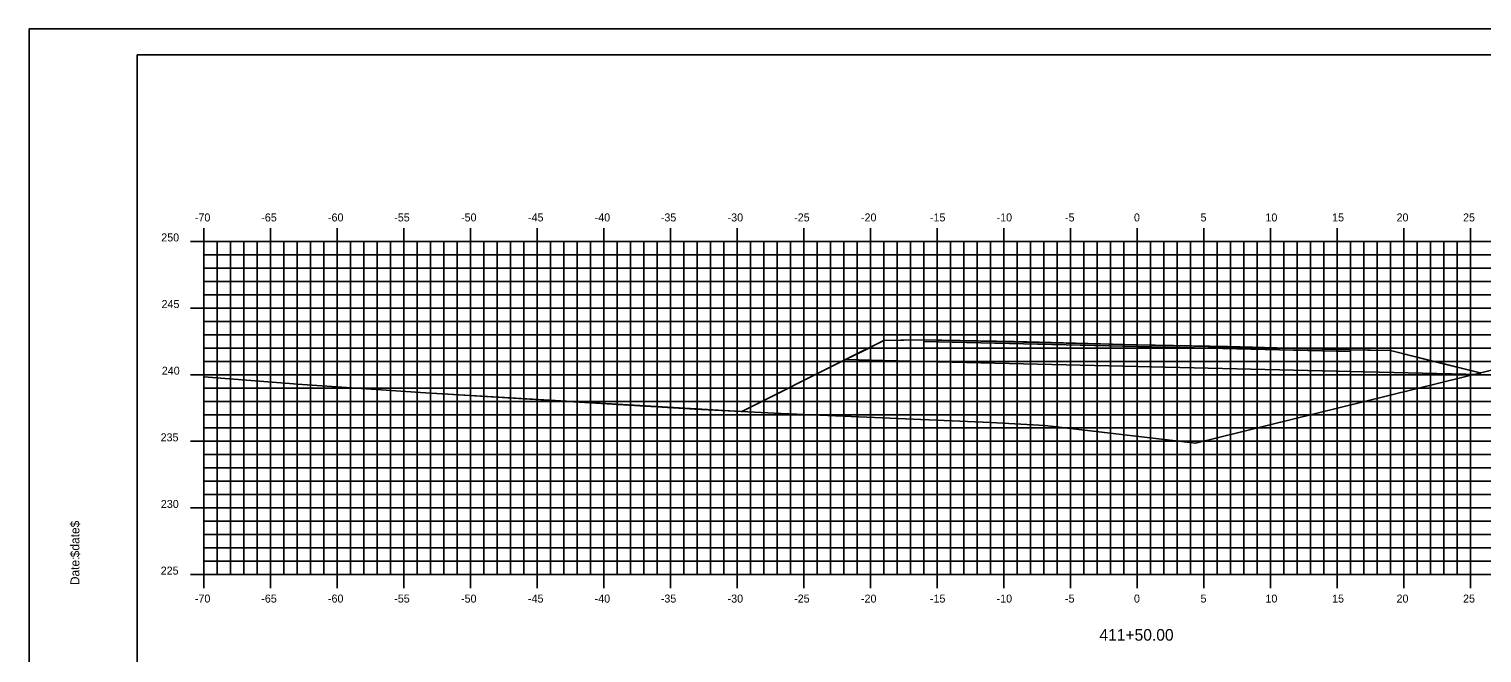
# Model space of a CAD drawing. Extents: x 1168600 to 1177589, y 610178 to 611246.
# Drawn here: x 1172219.5 to 1172328.4, y 610963.7 to 611010.5 of the extents above; entities that cross this region are included whole.
import ezdxf

# ---------------------------------------------------------------- set-up
doc = ezdxf.new("R2010")
doc.units = 0
for name, color, linetype in [('_Construction', 7, 'Continuous'), ('_Station Equation', 7, 'Continuous'), ('D_Roadway_Edge_TW', 7, 'Continuous'), ('D_Roadway_SubGrade', 7, 'Continuous'), ('D_Slope_Direction', 7, 'Continuous'), ('D_Text_Standard', 7, 'Continuous'), ('DIMENSIONS', 7, 'Continuous'), ('H_V ANNOTATION', 7, 'Continuous'), ('MAJOR', 7, 'Continuous'), ('MATCH LINES', 7, 'Continuous'), ('MINOR', 7, 'Continuous')]:
    doc.layers.add(name, color=color, linetype=linetype)

msp = doc.modelspace()

# ---------------------------------------------------------------- linework, layer by layer
at = {"layer": '_Construction'}
for p, q in [((1172387.56, 611008.6), (1172227.56, 611008.6)), ((1172227.56, 611008.6), (1172227.56, 610903.6))]:
    msp.add_line(p, q, dxfattribs=at)
msp.add_lwpolyline([(1172219.47, 610900.54), (1172389.47, 610900.54), (1172389.47, 611010.54), (1172219.47, 611010.54)], close=True, dxfattribs=at)
at = {"layer": '_Station Equation'}
for points in [[(1172232.56, 610984.43), (1172239.95, 610983.87), (1172249.2, 610983.24), (1172272.87, 610981.85), (1172272.87, 610981.85), (1172272.92, 610981.84), (1172280.7, 610985.74), (1172281.93, 610986.35), (1172283.56, 610987.16), (1172284.83, 610987.19), (1172286.56, 610987.22), (1172293.35, 610987.09), (1172302.56, 610986.85), (1172309.35, 610986.71), (1172318.56, 610986.47), (1172319.83, 610986.45), (1172321.56, 610986.41), (1172323.23, 610985.99), (1172324.01, 610985.8), (1172324.91, 610985.57), (1172328.27, 610984.73), (1172328.32, 610984.75), (1172328.33, 610984.75), (1172332.38, 610985.75)], [(1172232.56, 610984.43), (1172239.95, 610983.87), (1172249.2, 610983.24), (1172269.38, 610982.02), (1172275.87, 610981.7), (1172291.59, 610981.02), (1172295.63, 610980.79), (1172305.24, 610979.65), (1172306.94, 610979.46), (1172332.38, 610985.75)]]:
    msp.add_lwpolyline(points, dxfattribs=at)
at = {"layer": 'D_Roadway_Edge_TW'}
msp.add_lwpolyline([(1172318.56, 610986.35), (1172318.56, 610986.47), (1172302.56, 610986.85), (1172286.56, 610987.22), (1172286.56, 610987.1), (1172302.56, 610986.72)], close=True, dxfattribs=at)
at = {"layer": 'D_Roadway_SubGrade'}
for points in [[(1172286.56, 610987.22), (1172283.56, 610987.16), (1172280.7, 610985.74), (1172286.56, 610985.6)], [(1172318.56, 610984.85), (1172318.56, 610986.35), (1172302.56, 610986.72), (1172286.56, 610987.1), (1172286.56, 610985.6), (1172302.56, 610985.22)], [(1172318.56, 610986.47), (1172321.56, 610986.41), (1172328.27, 610984.73), (1172328.27, 610984.62), (1172318.56, 610984.85)]]:
    msp.add_lwpolyline(points, close=True, dxfattribs=at)
at = {"layer": 'D_Slope_Direction'}
msp.add_lwpolyline([(1172321.56, 610986.41), (1172328.27, 610984.73)], dxfattribs=at)
at = {"layer": 'D_Text_Standard'}
msp.add_lwpolyline([(1172272.92, 610981.84), (1172280.7, 610985.74), (1172281.93, 610986.35), (1172283.56, 610987.16), (1172284.83, 610987.19), (1172286.56, 610987.22), (1172293.35, 610987.09), (1172302.56, 610986.85), (1172309.35, 610986.71), (1172318.56, 610986.47), (1172319.83, 610986.45), (1172321.56, 610986.41), (1172323.23, 610985.99), (1172324.01, 610985.8), (1172324.91, 610985.57), (1172328.27, 610984.73)], dxfattribs=at)
at = {"layer": 'DIMENSIONS'}
msp.add_lwpolyline([(1172318.56, 610986.35), (1172318.56, 610986.35), (1172302.56, 610986.72), (1172286.56, 610987.1), (1172286.56, 610987.1), (1172302.56, 610986.72)], close=True, dxfattribs=at)
for points in [[(1172286.56, 610987.1), (1172286.56, 610987.1)], [(1172286.56, 610987.1), (1172286.56, 610987.1)], [(1172318.56, 610986.35), (1172318.56, 610986.35)], [(1172318.56, 610986.35), (1172318.56, 610986.35)]]:
    msp.add_lwpolyline(points, dxfattribs=at)
at = {"layer": 'MAJOR'}
for p, q in [((1172232.56, 610995.6), (1172232.56, 610994.6)), ((1172237.56, 610995.6), (1172237.56, 610994.6)), ((1172242.56, 610995.6), (1172242.56, 610994.6)), ((1172247.56, 610995.6), (1172247.56, 610994.6)), ((1172252.56, 610995.6), (1172252.56, 610994.6)), ((1172257.56, 610995.6), (1172257.56, 610994.6)), ((1172262.56, 610995.6), (1172262.56, 610994.6)), ((1172267.56, 610995.6), (1172267.56, 610994.6)), ((1172272.56, 610995.6), (1172272.56, 610994.6)), ((1172277.56, 610995.6), (1172277.56, 610994.6)), ((1172282.56, 610995.6), (1172282.56, 610994.6)), ((1172287.56, 610995.6), (1172287.56, 610994.6)), ((1172292.56, 610995.6), (1172292.56, 610994.6)), ((1172297.56, 610995.6), (1172297.56, 610994.6)), ((1172302.56, 610995.6), (1172302.56, 610994.6)), ((1172307.56, 610995.6), (1172307.56, 610994.6)), ((1172312.56, 610995.6), (1172312.56, 610994.6)), ((1172317.56, 610995.6), (1172317.56, 610994.6)), ((1172322.56, 610995.6), (1172322.56, 610994.6)), ((1172327.56, 610995.6), (1172327.56, 610994.6)), ((1172231.56, 610994.6), (1172232.56, 610994.6)), ((1172232.56, 610994.6), (1172372.56, 610994.6)), ((1172232.56, 610969.6), (1172232.56, 610994.6)), ((1172232.56, 610969.6), (1172232.56, 610994.6)), ((1172232.56, 610994.6), (1172372.56, 610994.6)), ((1172237.56, 610969.6), (1172237.56, 610994.6)), ((1172242.56, 610969.6), (1172242.56, 610994.6)), ((1172247.56, 610969.6), (1172247.56, 610994.6)), ((1172252.56, 610969.6), (1172252.56, 610994.6)), ((1172257.56, 610969.6), (1172257.56, 610994.6)), ((1172262.56, 610969.6), (1172262.56, 610994.6)), ((1172267.56, 610969.6), (1172267.56, 610994.6)), ((1172272.56, 610969.6), (1172272.56, 610994.6)), ((1172277.56, 610969.6), (1172277.56, 610994.6)), ((1172282.56, 610969.6), (1172282.56, 610994.6)), ((1172287.56, 610969.6), (1172287.56, 610994.6)), ((1172292.56, 610969.6), (1172292.56, 610994.6)), ((1172297.56, 610969.6), (1172297.56, 610994.6)), ((1172302.56, 610969.6), (1172302.56, 610994.6)), ((1172307.56, 610969.6), (1172307.56, 610994.6)), ((1172312.56, 610969.6), (1172312.56, 610994.6)), ((1172317.56, 610969.6), (1172317.56, 610994.6)), ((1172322.56, 610969.6), (1172322.56, 610994.6)), ((1172327.56, 610969.6), (1172327.56, 610994.6)), ((1172231.56, 610989.6), (1172232.56, 610989.6)), ((1172232.56, 610989.6), (1172372.56, 610989.6)), ((1172231.56, 610984.6), (1172232.56, 610984.6)), ((1172232.56, 610984.6), (1172372.56, 610984.6)), ((1172231.56, 610979.6), (1172232.56, 610979.6)), ((1172232.56, 610979.6), (1172372.56, 610979.6)), ((1172231.56, 610974.6), (1172232.56, 610974.6)), ((1172232.56, 610974.6), (1172372.56, 610974.6)), ((1172231.56, 610969.6), (1172232.56, 610969.6)), ((1172232.56, 610969.6), (1172372.56, 610969.6)), ((1172232.56, 610969.6), (1172372.56, 610969.6)), ((1172232.56, 610968.59), (1172232.56, 610969.6)), ((1172237.56, 610968.59), (1172237.56, 610969.6)), ((1172242.56, 610968.59), (1172242.56, 610969.6)), ((1172247.56, 610968.59), (1172247.56, 610969.6)), ((1172252.56, 610968.59), (1172252.56, 610969.6)), ((1172257.56, 610968.59), (1172257.56, 610969.6)), ((1172262.56, 610968.59), (1172262.56, 610969.6)), ((1172267.56, 610968.59), (1172267.56, 610969.6)), ((1172272.56, 610968.59), (1172272.56, 610969.6)), ((1172277.56, 610968.59), (1172277.56, 610969.6)), ((1172282.56, 610968.59), (1172282.56, 610969.6)), ((1172287.56, 610968.59), (1172287.56, 610969.6)), ((1172292.56, 610968.59), (1172292.56, 610969.6)), ((1172297.56, 610968.59), (1172297.56, 610969.6)), ((1172302.56, 610968.59), (1172302.56, 610969.6)), ((1172307.56, 610968.59), (1172307.56, 610969.6)), ((1172312.56, 610968.59), (1172312.56, 610969.6)), ((1172317.56, 610968.59), (1172317.56, 610969.6)), ((1172322.56, 610968.59), (1172322.56, 610969.6)), ((1172327.56, 610968.59), (1172327.56, 610969.6))]:
    msp.add_line(p, q, dxfattribs=at)
at = {"layer": 'MATCH LINES'}
for points in [[(1172286.56, 610987.22), (1172286.56, 610987.1)], [(1172318.56, 610986.47), (1172318.56, 610986.35)]]:
    msp.add_lwpolyline(points, dxfattribs=at)
at = {"layer": 'MINOR'}
for p, q in [((1172233.56, 610969.6), (1172233.56, 610994.6)), ((1172234.56, 610969.6), (1172234.56, 610994.6)), ((1172235.56, 610969.6), (1172235.56, 610994.6)), ((1172236.56, 610969.6), (1172236.56, 610994.6)), ((1172238.56, 610969.6), (1172238.56, 610994.6)), ((1172239.56, 610969.6), (1172239.56, 610994.6)), ((1172240.56, 610969.6), (1172240.56, 610994.6)), ((1172241.56, 610969.6), (1172241.56, 610994.6)), ((1172243.56, 610969.6), (1172243.56, 610994.6)), ((1172244.56, 610969.6), (1172244.56, 610994.6)), ((1172245.56, 610969.6), (1172245.56, 610994.6)), ((1172246.56, 610969.6), (1172246.56, 610994.6)), ((1172248.56, 610969.6), (1172248.56, 610994.6)), ((1172249.56, 610969.6), (1172249.56, 610994.6)), ((1172250.56, 610969.6), (1172250.56, 610994.6)), ((1172251.56, 610969.6), (1172251.56, 610994.6)), ((1172253.56, 610969.6), (1172253.56, 610994.6)), ((1172254.56, 610969.6), (1172254.56, 610994.6)), ((1172255.56, 610969.6), (1172255.56, 610994.6)), ((1172256.56, 610969.6), (1172256.56, 610994.6)), ((1172258.56, 610969.6), (1172258.56, 610994.6)), ((1172259.56, 610969.6), (1172259.56, 610994.6)), ((1172260.56, 610969.6), (1172260.56, 610994.6)), ((1172261.56, 610969.6), (1172261.56, 610994.6)), ((1172263.56, 610969.6), (1172263.56, 610994.6)), ((1172264.56, 610969.6), (1172264.56, 610994.6)), ((1172265.56, 610969.6), (1172265.56, 610994.6)), ((1172266.56, 610969.6), (1172266.56, 610994.6)), ((1172268.56, 610969.6), (1172268.56, 610994.6)), ((1172269.56, 610969.6), (1172269.56, 610994.6)), ((1172270.56, 610969.6), (1172270.56, 610994.6)), ((1172271.56, 610969.6), (1172271.56, 610994.6)), ((1172273.56, 610969.6), (1172273.56, 610994.6)), ((1172274.56, 610969.6), (1172274.56, 610994.6)), ((1172275.56, 610969.6), (1172275.56, 610994.6)), ((1172276.56, 610969.6), (1172276.56, 610994.6)), ((1172278.56, 610969.6), (1172278.56, 610994.6)), ((1172279.56, 610969.6), (1172279.56, 610994.6)), ((1172280.56, 610969.6), (1172280.56, 610994.6)), ((1172281.56, 610969.6), (1172281.56, 610994.6)), ((1172283.56, 610969.6), (1172283.56, 610994.6)), ((1172284.56, 610969.6), (1172284.56, 610994.6)), ((1172285.56, 610969.6), (1172285.56, 610994.6)), ((1172286.56, 610969.6), (1172286.56, 610994.6)), ((1172288.56, 610969.6), (1172288.56, 610994.6)), ((1172289.56, 610969.6), (1172289.56, 610994.6)), ((1172290.56, 610969.6), (1172290.56, 610994.6)), ((1172291.56, 610969.6), (1172291.56, 610994.6)), ((1172293.56, 610969.6), (1172293.56, 610994.6)), ((1172294.56, 610969.6), (1172294.56, 610994.6)), ((1172295.56, 610969.6), (1172295.56, 610994.6)), ((1172296.56, 610969.6), (1172296.56, 610994.6)), ((1172298.56, 610969.6), (1172298.56, 610994.6)), ((1172299.56, 610969.6), (1172299.56, 610994.6)), ((1172300.56, 610969.6), (1172300.56, 610994.6)), ((1172301.56, 610969.6), (1172301.56, 610994.6)), ((1172303.56, 610969.6), (1172303.56, 610994.6)), ((1172304.56, 610969.6), (1172304.56, 610994.6)), ((1172305.56, 610969.6), (1172305.56, 610994.6)), ((1172306.56, 610969.6), (1172306.56, 610994.6)), ((1172308.56, 610969.6), (1172308.56, 610994.6)), ((1172309.56, 610969.6), (1172309.56, 610994.6)), ((1172310.56, 610969.6), (1172310.56, 610994.6)), ((1172311.56, 610969.6), (1172311.56, 610994.6)), ((1172313.56, 610969.6), (1172313.56, 610994.6)), ((1172314.56, 610969.6), (1172314.56, 610994.6)), ((1172315.56, 610969.6), (1172315.56, 610994.6)), ((1172316.56, 610969.6), (1172316.56, 610994.6)), ((1172318.56, 610969.6), (1172318.56, 610994.6)), ((1172319.56, 610969.6), (1172319.56, 610994.6)), ((1172320.56, 610969.6), (1172320.56, 610994.6)), ((1172321.56, 610969.6), (1172321.56, 610994.6)), ((1172323.56, 610969.6), (1172323.56, 610994.6)), ((1172324.56, 610969.6), (1172324.56, 610994.6)), ((1172325.56, 610969.6), (1172325.56, 610994.6)), ((1172326.56, 610969.6), (1172326.56, 610994.6)), ((1172232.56, 610993.6), (1172372.56, 610993.6)), ((1172232.56, 610993.6), (1172233.56, 610993.6)), ((1172232.56, 610992.6), (1172372.56, 610992.6)), ((1172232.56, 610992.6), (1172233.56, 610992.6)), ((1172232.56, 610991.6), (1172372.56, 610991.6)), ((1172232.56, 610991.6), (1172233.56, 610991.6)), ((1172232.56, 610990.6), (1172372.56, 610990.6)), ((1172232.56, 610990.6), (1172233.56, 610990.6)), ((1172232.56, 610988.6), (1172372.56, 610988.6)), ((1172232.56, 610988.6), (1172233.56, 610988.6)), ((1172232.56, 610987.6), (1172372.56, 610987.6)), ((1172232.56, 610987.6), (1172233.56, 610987.6)), ((1172232.56, 610986.6), (1172372.56, 610986.6)), ((1172232.56, 610986.6), (1172233.56, 610986.6)), ((1172232.56, 610985.6), (1172372.56, 610985.6)), ((1172232.56, 610985.6), (1172233.56, 610985.6)), ((1172232.56, 610983.6), (1172372.56, 610983.6)), ((1172232.56, 610983.6), (1172233.56, 610983.6)), ((1172232.56, 610982.6), (1172372.56, 610982.6)), ((1172232.56, 610982.6), (1172233.56, 610982.6)), ((1172232.56, 610981.6), (1172372.56, 610981.6)), ((1172232.56, 610981.6), (1172233.56, 610981.6)), ((1172232.56, 610980.6), (1172372.56, 610980.6)), ((1172232.56, 610980.6), (1172233.56, 610980.6)), ((1172232.56, 610978.6), (1172372.56, 610978.6)), ((1172232.56, 610978.6), (1172233.56, 610978.6)), ((1172232.56, 610977.6), (1172372.56, 610977.6)), ((1172232.56, 610977.6), (1172233.56, 610977.6)), ((1172232.56, 610976.6), (1172372.56, 610976.6)), ((1172232.56, 610976.6), (1172233.56, 610976.6)), ((1172232.56, 610975.6), (1172372.56, 610975.6)), ((1172232.56, 610975.6), (1172233.56, 610975.6)), ((1172232.56, 610973.6), (1172372.56, 610973.6)), ((1172232.56, 610973.6), (1172233.56, 610973.6)), ((1172232.56, 610972.6), (1172372.56, 610972.6)), ((1172232.56, 610972.6), (1172233.56, 610972.6)), ((1172232.56, 610971.6), (1172372.56, 610971.6)), ((1172232.56, 610971.6), (1172233.56, 610971.6)), ((1172232.56, 610970.6), (1172372.56, 610970.6)), ((1172232.56, 610970.6), (1172233.56, 610970.6))]:
    msp.add_line(p, q, dxfattribs=at)

# ---------------------------------------------------------------- texts
at = {"layer": '_Construction'}
for s, p in [('$date$', (1172223.24, 610970.9)), ('Date:', (1172223.24, 610968.81))]:
    msp.add_text(s, height=0.67, rotation=90, dxfattribs=at).set_placement(p)
at = {"layer": 'H_V ANNOTATION'}
for s, height, p in [('-70', 0.6, (1172231.9, 610996.1)), ('-65', 0.6, (1172236.88, 610996.1)), ('-60', 0.6, (1172241.88, 610996.1)), ('-55', 0.6, (1172246.85, 610996.1)), ('-50', 0.6, (1172251.86, 610996.1)), ('-45', 0.6, (1172256.88, 610996.1)), ('-40', 0.6, (1172261.88, 610996.1)), ('-35', 0.6, (1172266.84, 610996.1)), ('-30', 0.6, (1172271.85, 610996.1)), ('-25', 0.6, (1172276.84, 610996.1)), ('-20', 0.6, (1172281.85, 610996.1)), ('-15', 0.6, (1172287.02, 610996.1)), ('-10', 0.6, (1172292.02, 610996.1)), ('-5', 0.6, (1172297.15, 610996.1)), ('0', 0.6, (1172302.32, 610996.1)), ('5', 0.6, (1172307.31, 610996.1)), ('10', 0.6, (1172312.18, 610996.1)), ('15', 0.6, (1172317.18, 610996.1)), ('20', 0.6, (1172322.01, 610996.1)), ('25', 0.6, (1172327, 610996.1)), ('250', 0.6, (1172229.38, 610994.6)), ('245', 0.6, (1172229.4, 610989.6)), ('240', 0.6, (1172229.42, 610984.6)), ('235', 0.6, (1172229.33, 610979.6)), ('230', 0.6, (1172229.35, 610974.6)), ('225', 0.6, (1172229.34, 610969.6)), ('-70', 0.6, (1172231.9, 610967.5)), ('-65', 0.6, (1172236.88, 610967.5)), ('-60', 0.6, (1172241.88, 610967.5)), ('-55', 0.6, (1172246.85, 610967.5)), ('-50', 0.6, (1172251.86, 610967.5)), ('-45', 0.6, (1172256.88, 610967.5)), ('-40', 0.6, (1172261.88, 610967.5)), ('-35', 0.6, (1172266.84, 610967.5)), ('-30', 0.6, (1172271.85, 610967.5)), ('-25', 0.6, (1172276.84, 610967.5)), ('-20', 0.6, (1172281.85, 610967.5)), ('-15', 0.6, (1172287.02, 610967.5)), ('-10', 0.6, (1172292.02, 610967.5)), ('-5', 0.6, (1172297.15, 610967.5)), ('0', 0.6, (1172302.32, 610967.5)), ('5', 0.6, (1172307.31, 610967.5)), ('10', 0.6, (1172312.18, 610967.5)), ('15', 0.6, (1172317.18, 610967.5)), ('20', 0.6, (1172322.01, 610967.5)), ('25', 0.6, (1172327, 610967.5)), ('411+50.00', 0.875, (1172299.73, 610964.64))]:
    msp.add_text(s, height=height, dxfattribs=at).set_placement(p)

doc.saveas('drawing.dxf')
